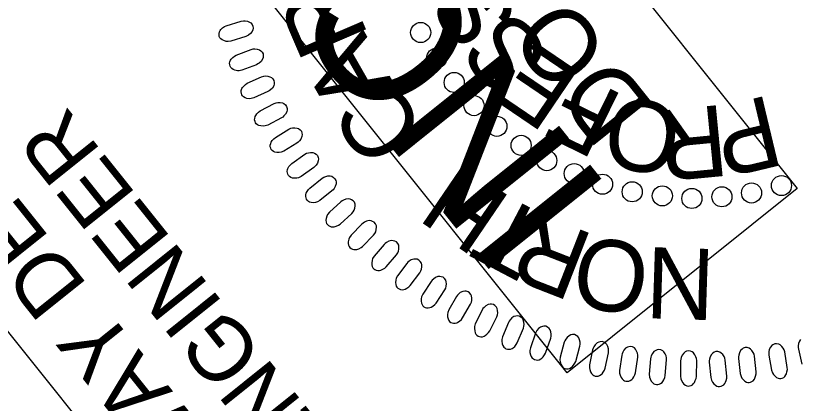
# Model space of a CAD drawing. Extents: x 473437 to 475344, y 504319 to 506318.
# Drawn here: x 473584.9 to 473647.5, y 505540.2 to 505571.1 of the extents above; entities that cross this region are included whole.
import ezdxf

# ---------------------------------------------------------------- set-up
doc = ezdxf.new("R2010")
doc.units = 0
for name, color, linetype in [('Sheet PE Seal Cell', 7, 'Continuous'), ('Sheet Plan CELL', 7, 'Continuous'), ('Sheet Sticker Incomplete CELL', 7, 'Continuous')]:
    doc.layers.add(name, color=color, linetype=linetype)

msp = doc.modelspace()

# ---------------------------------------------------------------- linework, layer by layer
at = {"layer": 'Sheet PE Seal Cell'}
for points in [[(473603.245, 505569.425), (473602.073, 505569.065), (473601.852, 505569.037), (473601.703, 505569.046), (473601.508, 505569.103), (473601.374, 505569.164), (473601.265, 505569.248), (473601.197, 505569.336), (473601.144, 505569.437), (473601.131, 505569.55), (473601.125, 505569.674), (473601.151, 505569.791), (473601.216, 505569.921), (473601.274, 505570.001), (473601.397, 505570.109), (473601.551, 505570.22), (473601.698, 505570.288), (473602.897, 505570.663), (473603.066, 505570.691), (473603.212, 505570.689), (473603.391, 505570.65), (473603.558, 505570.585), (473603.662, 505570.515), (473603.765, 505570.382), (473603.828, 505570.245), (473603.834, 505570.091), (473603.817, 505569.976), (473603.759, 505569.825), (473603.631, 505569.661), (473603.48, 505569.544), (473603.365, 505569.478)], [(473604.098, 505567.183), (473602.95, 505566.75), (473602.732, 505566.708), (473602.583, 505566.708), (473602.384, 505566.753), (473602.248, 505566.805), (473602.133, 505566.882), (473602.059, 505566.966), (473602.001, 505567.064), (473601.98, 505567.176), (473601.966, 505567.298), (473601.985, 505567.418), (473602.041, 505567.55), (473602.095, 505567.634), (473602.211, 505567.75), (473602.358, 505567.869), (473602.5, 505567.947), (473603.673, 505568.397), (473603.839, 505568.436), (473603.986, 505568.443), (473604.167, 505568.416), (473604.337, 505568.359), (473604.446, 505568.297), (473604.558, 505568.171), (473604.629, 505568.038), (473604.644, 505567.884), (473604.634, 505567.769), (473604.586, 505567.615), (473604.47, 505567.443), (473604.325, 505567.316), (473604.214, 505567.243)], [(473605.019, 505565.038), (473603.9, 505564.534), (473603.685, 505564.478), (473603.536, 505564.468), (473603.335, 505564.501), (473603.196, 505564.544), (473603.077, 505564.614), (473602.997, 505564.693), (473602.932, 505564.787), (473602.905, 505564.897), (473602.883, 505565.019), (473602.895, 505565.138), (473602.943, 505565.275), (473602.991, 505565.362), (473603.1, 505565.485), (473603.239, 505565.613), (473603.375, 505565.7), (473604.518, 505566.222), (473604.682, 505566.271), (473604.827, 505566.287), (473605.009, 505566.272), (473605.183, 505566.227), (473605.296, 505566.171), (473605.415, 505566.052), (473605.494, 505565.924), (473605.519, 505565.772), (473605.517, 505565.656), (473605.478, 505565.499), (473605.373, 505565.32), (473605.236, 505565.185), (473605.131, 505565.105)], [(473606.089, 505562.942), (473605.005, 505562.369), (473604.793, 505562.3), (473604.645, 505562.281), (473604.443, 505562.301), (473604.301, 505562.335), (473604.178, 505562.397), (473604.094, 505562.471), (473604.023, 505562.561), (473603.989, 505562.669), (473603.959, 505562.789), (473603.963, 505562.91), (473604.003, 505563.049), (473604.045, 505563.138), (473604.146, 505563.268), (473604.277, 505563.405), (473604.408, 505563.5), (473605.515, 505564.093), (473605.675, 505564.152), (473605.82, 505564.178), (473606.003, 505564.173), (473606.179, 505564.139), (473606.295, 505564.09), (473606.421, 505563.98), (473606.508, 505563.857), (473606.543, 505563.706), (473606.548, 505563.59), (473606.519, 505563.431), (473606.425, 505563.246), (473606.298, 505563.103), (473606.197, 505563.016)], [(473607.327, 505560.936), (473606.281, 505560.297), (473606.074, 505560.214), (473605.928, 505560.186), (473605.725, 505560.193), (473605.58, 505560.219), (473605.454, 505560.273), (473605.365, 505560.341), (473605.29, 505560.426), (473605.248, 505560.533), (473605.211, 505560.65), (473605.208, 505560.77), (473605.238, 505560.912), (473605.275, 505561.004), (473605.367, 505561.14), (473605.49, 505561.284), (473605.614, 505561.387), (473606.682, 505562.049), (473606.838, 505562.118), (473606.98, 505562.153), (473607.164, 505562.16), (473607.341, 505562.137), (473607.46, 505562.096), (473607.593, 505561.993), (473607.688, 505561.876), (473607.732, 505561.727), (473607.744, 505561.612), (473607.726, 505561.451), (473607.643, 505561.261), (473607.525, 505561.11), (473607.43, 505561.017)], [(473608.667, 505558.983), (473607.662, 505558.278), (473607.461, 505558.182), (473607.317, 505558.145), (473607.114, 505558.14), (473606.968, 505558.156), (473606.838, 505558.202), (473606.746, 505558.265), (473606.665, 505558.346), (473606.617, 505558.449), (473606.573, 505558.564), (473606.562, 505558.684), (473606.583, 505558.827), (473606.614, 505558.921), (473606.698, 505559.063), (473606.811, 505559.214), (473606.928, 505559.325), (473607.953, 505560.052), (473608.104, 505560.132), (473608.244, 505560.175), (473608.426, 505560.193), (473608.605, 505560.181), (473608.727, 505560.148), (473608.866, 505560.054), (473608.968, 505559.943), (473609.021, 505559.797), (473609.04, 505559.683), (473609.031, 505559.522), (473608.961, 505559.327), (473608.853, 505559.168), (473608.764, 505559.069)], [(473610.12, 505557.124), (473609.162, 505556.358), (473608.968, 505556.25), (473608.825, 505556.204), (473608.623, 505556.186), (473608.477, 505556.193), (473608.344, 505556.231), (473608.248, 505556.287), (473608.162, 505556.363), (473608.108, 505556.462), (473608.056, 505556.575), (473608.038, 505556.693), (473608.05, 505556.838), (473608.076, 505556.935), (473608.15, 505557.08), (473608.253, 505557.24), (473608.364, 505557.357), (473609.34, 505558.147), (473609.487, 505558.236), (473609.624, 505558.288), (473609.804, 505558.317), (473609.984, 505558.317), (473610.106, 505558.291), (473610.251, 505558.205), (473610.36, 505558.101), (473610.422, 505557.96), (473610.449, 505557.847), (473610.451, 505557.685), (473610.393, 505557.486), (473610.295, 505557.321), (473610.212, 505557.217)], [(473610.824, 505556.259), (473609.916, 505555.434), (473609.779, 505555.259), (473609.711, 505555.127), (473609.66, 505554.929), (473609.644, 505554.784), (473609.661, 505554.647), (473609.701, 505554.543), (473609.763, 505554.446), (473609.853, 505554.377), (473609.955, 505554.309), (473610.07, 505554.271), (473610.214, 505554.261), (473610.313, 505554.271), (473610.469, 505554.321), (473610.643, 505554.397), (473610.775, 505554.488), (473611.711, 505555.328), (473611.821, 505555.458), (473611.894, 505555.585), (473611.952, 505555.759), (473611.98, 505555.936), (473611.974, 505556.061), (473611.912, 505556.218), (473611.827, 505556.342), (473611.696, 505556.426), (473611.589, 505556.47), (473611.43, 505556.496), (473611.224, 505556.471), (473611.046, 505556.4), (473610.93, 505556.335)], [(473612.506, 505554.482), (473611.652, 505553.602), (473611.525, 505553.418), (473611.466, 505553.282), (473611.428, 505553.082), (473611.421, 505552.935), (473611.446, 505552.801), (473611.494, 505552.699), (473611.56, 505552.606), (473611.655, 505552.543), (473611.761, 505552.481), (473611.878, 505552.451), (473612.022, 505552.449), (473612.121, 505552.465), (473612.273, 505552.525), (473612.441, 505552.613), (473612.569, 505552.711), (473613.449, 505553.608), (473613.551, 505553.745), (473613.616, 505553.877), (473613.663, 505554.054), (473613.68, 505554.232), (473613.665, 505554.357), (473613.595, 505554.509), (473613.501, 505554.628), (473613.366, 505554.703), (473613.256, 505554.74), (473613.096, 505554.757), (473612.892, 505554.719), (473612.719, 505554.637), (473612.607, 505554.564)], [(473614.281, 505552.853), (473613.484, 505551.921), (473613.37, 505551.73), (473613.318, 505551.59), (473613.293, 505551.388), (473613.296, 505551.242), (473613.329, 505551.108), (473613.383, 505551.01), (473613.455, 505550.921), (473613.553, 505550.864), (473613.663, 505550.809), (473613.782, 505550.786), (473613.927, 505550.794), (473614.024, 505550.816), (473614.172, 505550.886), (473614.334, 505550.983), (473614.455, 505551.09), (473615.277, 505552.04), (473615.371, 505552.183), (473615.428, 505552.318), (473615.463, 505552.498), (473615.468, 505552.677), (473615.446, 505552.801), (473615.366, 505552.949), (473615.265, 505553.06), (473615.126, 505553.128), (473615.014, 505553.158), (473614.853, 505553.165), (473614.652, 505553.114), (473614.484, 505553.021), (473614.377, 505552.942)], [(473616.09, 505551.348), (473615.353, 505550.368), (473615.251, 505550.17), (473615.208, 505550.027), (473615.196, 505549.824), (473615.208, 505549.678), (473615.25, 505549.547), (473615.309, 505549.451), (473615.387, 505549.369), (473615.488, 505549.317), (473615.602, 505549.269), (473615.722, 505549.254), (473615.865, 505549.271), (473615.961, 505549.298), (473616.105, 505549.378), (473616.26, 505549.485), (473616.374, 505549.599), (473617.136, 505550.599), (473617.22, 505550.748), (473617.268, 505550.887), (473617.292, 505551.068), (473617.286, 505551.247), (473617.256, 505551.369), (473617.167, 505551.512), (473617.059, 505551.617), (473616.916, 505551.676), (473616.803, 505551.699), (473616.641, 505551.695), (473616.444, 505551.631), (473616.282, 505551.528), (473616.18, 505551.443)], [(473618.033, 505549.914), (473617.359, 505548.889), (473617.269, 505548.686), (473617.236, 505548.54), (473617.236, 505548.337), (473617.257, 505548.192), (473617.307, 505548.064), (473617.373, 505547.972), (473617.455, 505547.894), (473617.56, 505547.849), (473617.676, 505547.809), (473617.796, 505547.801), (473617.939, 505547.826), (473618.033, 505547.861), (473618.171, 505547.948), (473618.32, 505548.066), (473618.427, 505548.187), (473619.123, 505549.232), (473619.197, 505549.386), (473619.237, 505549.527), (473619.25, 505549.71), (473619.233, 505549.888), (473619.196, 505550.008), (473619.097, 505550.145), (473618.983, 505550.243), (473618.837, 505550.292), (473618.721, 505550.308), (473618.561, 505550.295), (473618.368, 505550.219), (473618.213, 505550.106), (473618.116, 505550.014)], [(473620.045, 505548.706), (473619.437, 505547.641), (473619.361, 505547.431), (473619.336, 505547.285), (473619.35, 505547.082), (473619.379, 505546.938), (473619.437, 505546.814), (473619.508, 505546.727), (473619.596, 505546.654), (473619.703, 505546.616), (473619.822, 505546.582), (473619.942, 505546.582), (473620.083, 505546.617), (473620.174, 505546.657), (473620.307, 505546.753), (473620.448, 505546.879), (473620.546, 505547.006), (473621.176, 505548.094), (473621.241, 505548.252), (473621.271, 505548.396), (473621.273, 505548.579), (473621.245, 505548.755), (473621.2, 505548.873), (473621.093, 505549.003), (473620.973, 505549.094), (473620.824, 505549.133), (473620.708, 505549.142), (473620.548, 505549.119), (473620.36, 505549.032), (473620.213, 505548.908), (473620.123, 505548.811)], [(473622.097, 505547.635), (473621.556, 505546.534), (473621.493, 505546.321), (473621.479, 505546.172), (473621.504, 505545.971), (473621.544, 505545.83), (473621.609, 505545.709), (473621.685, 505545.627), (473621.777, 505545.559), (473621.887, 505545.528), (473622.007, 505545.502), (473622.127, 505545.509), (473622.265, 505545.553), (473622.354, 505545.598), (473622.48, 505545.703), (473622.613, 505545.838), (473622.704, 505545.971), (473623.264, 505547.096), (473623.319, 505547.258), (473623.34, 505547.403), (473623.329, 505547.586), (473623.29, 505547.761), (473623.238, 505547.875), (473623.124, 505547.998), (473622.998, 505548.082), (473622.847, 505548.111), (473622.731, 505548.113), (473622.573, 505548.08), (473622.391, 505547.98), (473622.251, 505547.849), (473622.167, 505547.745)], [(473624.19, 505546.643), (473623.72, 505545.51), (473623.67, 505545.292), (473623.665, 505545.144), (473623.703, 505544.944), (473623.751, 505544.806), (473623.824, 505544.689), (473623.905, 505544.612), (473624.001, 505544.551), (473624.112, 505544.526), (473624.234, 505544.508), (473624.354, 505544.523), (473624.489, 505544.575), (473624.575, 505544.626), (473624.694, 505544.738), (473624.819, 505544.881), (473624.9, 505545.02), (473625.389, 505546.178), (473625.433, 505546.342), (473625.445, 505546.489), (473625.424, 505546.67), (473625.374, 505546.842), (473625.315, 505546.953), (473625.192, 505547.069), (473625.062, 505547.144), (473624.909, 505547.165), (473624.793, 505547.159), (473624.637, 505547.116), (473624.462, 505547.005), (473624.331, 505546.865), (473624.254, 505546.757)], [(473626.342, 505545.781), (473625.944, 505544.621), (473625.908, 505544.401), (473625.912, 505544.253), (473625.962, 505544.055), (473626.019, 505543.92), (473626.099, 505543.809), (473626.185, 505543.737), (473626.285, 505543.682), (473626.398, 505543.663), (473626.52, 505543.653), (473626.639, 505543.676), (473626.77, 505543.736), (473626.853, 505543.792), (473626.965, 505543.912), (473627.079, 505544.063), (473627.153, 505544.206), (473627.568, 505545.392), (473627.602, 505545.56), (473627.605, 505545.707), (473627.571, 505545.887), (473627.511, 505546.055), (473627.445, 505546.162), (473627.316, 505546.269), (473627.181, 505546.337), (473627.027, 505546.348), (473626.911, 505546.334), (473626.759, 505546.282), (473626.591, 505546.16), (473626.469, 505546.011), (473626.399, 505545.899)], [(473628.65, 505545.066), (473628.325, 505543.883), (473628.303, 505543.661), (473628.316, 505543.513), (473628.38, 505543.319), (473628.445, 505543.188), (473628.532, 505543.082), (473628.622, 505543.015), (473628.725, 505542.967), (473628.838, 505542.956), (473628.961, 505542.953), (473629.078, 505542.983), (473629.206, 505543.052), (473629.284, 505543.113), (473629.389, 505543.24), (473629.494, 505543.396), (473629.558, 505543.544), (473629.898, 505544.754), (473629.921, 505544.924), (473629.915, 505545.07), (473629.871, 505545.248), (473629.799, 505545.412), (473629.727, 505545.515), (473629.591, 505545.614), (473629.452, 505545.673), (473629.297, 505545.674), (473629.184, 505545.653), (473629.034, 505545.591), (473628.874, 505545.459), (473628.762, 505545.304), (473628.699, 505545.186)], [(473630.909, 505544.465), (473630.66, 505543.264), (473630.652, 505543.042), (473630.674, 505542.895), (473630.75, 505542.706), (473630.822, 505542.579), (473630.916, 505542.478), (473631.01, 505542.418), (473631.116, 505542.375), (473631.23, 505542.372), (473631.353, 505542.377), (473631.468, 505542.414), (473631.591, 505542.491), (473631.665, 505542.556), (473631.762, 505542.689), (473631.857, 505542.852), (473631.912, 505543.005), (473632.175, 505544.233), (473632.187, 505544.404), (473632.171, 505544.549), (473632.116, 505544.724), (473632.035, 505544.883), (473631.956, 505544.981), (473631.814, 505545.072), (473631.672, 505545.122), (473631.518, 505545.113), (473631.405, 505545.086), (473631.26, 505545.014), (473631.109, 505544.872), (473631.007, 505544.71), (473630.951, 505544.589)], [(473644.961, 505544.048), (473645.17, 505542.839), (473645.245, 505542.63), (473645.32, 505542.501), (473645.46, 505542.353), (473645.574, 505542.261), (473645.698, 505542.202), (473645.808, 505542.181), (473645.922, 505542.18), (473646.029, 505542.219), (473646.142, 505542.269), (473646.235, 505542.346), (473646.32, 505542.462), (473646.366, 505542.551), (473646.407, 505542.71), (473646.435, 505542.897), (473646.43, 505543.058), (473646.222, 505544.297), (473646.171, 505544.46), (473646.103, 505544.59), (473645.987, 505544.732), (473645.853, 505544.851), (473645.743, 505544.913), (473645.578, 505544.945), (473645.428, 505544.938), (473645.287, 505544.874), (473645.193, 505544.807), (473645.084, 505544.687), (473644.996, 505544.5), (473644.96, 505544.311), (473644.953, 505544.178)], [(473633.228, 505544.031), (473633.054, 505542.817), (473633.06, 505542.595), (473633.092, 505542.448), (473633.179, 505542.265), (473633.259, 505542.143), (473633.359, 505542.048), (473633.457, 505541.993), (473633.565, 505541.958), (473633.679, 505541.962), (473633.802, 505541.975), (473633.914, 505542.019), (473634.032, 505542.103), (473634.103, 505542.173), (473634.19, 505542.312), (473634.275, 505542.481), (473634.319, 505542.635), (473634.505, 505543.879), (473634.507, 505544.05), (473634.482, 505544.194), (473634.416, 505544.365), (473634.325, 505544.52), (473634.24, 505544.612), (473634.093, 505544.693), (473633.947, 505544.734), (473633.794, 505544.715), (473633.683, 505544.681), (473633.543, 505544.601), (473633.401, 505544.45), (473633.309, 505544.281), (473633.261, 505544.158)], [(473635.523, 505543.739), (473635.426, 505542.517), (473635.446, 505542.295), (473635.487, 505542.151), (473635.585, 505541.973), (473635.673, 505541.856), (473635.779, 505541.768), (473635.88, 505541.72), (473635.99, 505541.691), (473636.103, 505541.702), (473636.225, 505541.723), (473636.334, 505541.773), (473636.446, 505541.865), (473636.512, 505541.94), (473636.592, 505542.083), (473636.665, 505542.258), (473636.701, 505542.415), (473636.807, 505543.667), (473636.798, 505543.837), (473636.765, 505543.98), (473636.688, 505544.147), (473636.587, 505544.294), (473636.497, 505544.382), (473636.345, 505544.454), (473636.198, 505544.486), (473636.045, 505544.458), (473635.937, 505544.417), (473635.802, 505544.327), (473635.67, 505544.167), (473635.588, 505543.994), (473635.549, 505543.867)], [(473637.926, 505543.596), (473637.906, 505542.37), (473637.94, 505542.149), (473637.99, 505542.009), (473638.099, 505541.837), (473638.194, 505541.726), (473638.305, 505541.645), (473638.409, 505541.604), (473638.521, 505541.582), (473638.633, 505541.599), (473638.753, 505541.628), (473638.859, 505541.685), (473638.965, 505541.783), (473639.027, 505541.862), (473639.096, 505542.011), (473639.159, 505542.19), (473639.184, 505542.348), (473639.212, 505543.605), (473639.193, 505543.775), (473639.15, 505543.915), (473639.063, 505544.076), (473638.953, 505544.217), (473638.857, 505544.299), (473638.701, 505544.361), (473638.553, 505544.383), (473638.402, 505544.346), (473638.297, 505544.298), (473638.168, 505544.201), (473638.046, 505544.033), (473637.975, 505543.855), (473637.944, 505543.725)], [(473640.208, 505543.469), (473640.332, 505542.249), (473640.392, 505542.035), (473640.457, 505541.901), (473640.586, 505541.743), (473640.694, 505541.644), (473640.813, 505541.577), (473640.921, 505541.547), (473641.035, 505541.539), (473641.145, 505541.57), (473641.261, 505541.612), (473641.359, 505541.681), (473641.453, 505541.791), (473641.504, 505541.877), (473641.556, 505542.033), (473641.598, 505542.218), (473641.604, 505542.378), (473641.484, 505543.629), (473641.445, 505543.796), (473641.386, 505543.93), (473641.28, 505544.08), (473641.155, 505544.207), (473641.05, 505544.276), (473640.888, 505544.32), (473640.737, 505544.325), (473640.592, 505544.27), (473640.493, 505544.21), (473640.377, 505544.098), (473640.275, 505543.918), (473640.226, 505543.732), (473640.21, 505543.6)], [(473642.546, 505543.785), (473642.68, 505542.566), (473642.741, 505542.352), (473642.808, 505542.219), (473642.938, 505542.062), (473643.046, 505541.964), (473643.166, 505541.896), (473643.275, 505541.869), (473643.389, 505541.861), (473643.498, 505541.893), (473643.613, 505541.936), (473643.711, 505542.007), (473643.804, 505542.117), (473643.855, 505542.203), (473643.906, 505542.359), (473643.946, 505542.544), (473643.95, 505542.705), (473643.821, 505543.955), (473643.78, 505544.121), (473643.72, 505544.255), (473643.614, 505544.404), (473643.487, 505544.53), (473643.382, 505544.599), (473643.219, 505544.641), (473643.068, 505544.645), (473642.924, 505544.589), (473642.826, 505544.528), (473642.71, 505544.415), (473642.61, 505544.234), (473642.562, 505544.048), (473642.547, 505543.915)]]:
    msp.add_lwpolyline(points, close=True, dxfattribs=at)
msp.add_lwpolyline([(473647.495, 505545.281), (473647.395, 505545.155), (473647.318, 505544.962), (473647.295, 505544.772), (473647.296, 505544.639), (473647.311, 505544.509), (473647.597, 505543.316)], dxfattribs=at)
for centre in [(473617.199, 505569.751), (473618.474, 505567.711), (473619.872, 505565.771), (473621.452, 505563.924), (473623.28, 505562.276), (473625.207, 505560.759), (473627.253, 505559.54), (473629.44, 505558.505), (473631.698, 505557.66), (473645.966, 505557.55), (473634.067, 505557.057), (473636.468, 505556.734), (473638.825, 505556.529), (473641.22, 505556.66), (473643.578, 505556.965)]:
    msp.add_circle(centre, 0.801, dxfattribs=at)
at = {"layer": 'Sheet Plan CELL'}
msp.add_lwpolyline([(473619.893, 505501.436), (473557.377, 505579.55), (473645.22, 505649.853), (473707.709, 505571.734)], close=True, dxfattribs=at)
at = {"layer": 'Sheet Sticker Incomplete CELL'}
msp.add_lwpolyline([(473647.22, 505557.313), (473628.873, 505542.629), (473537.02, 505657.398), (473555.367, 505672.082)], close=True, dxfattribs=at)

# ---------------------------------------------------------------- texts
at = {"layer": 'Sheet PE Seal Cell'}
for s, rotation, p in [('S', 122.02046, (473625.236, 505570.88)), ('R', 113.28019, (473613.087, 505569.434)), ('S', 129.96025, (473627.728, 505567.929)), ('A', 119.76954, (473615.095, 505565.653)), ('E', 145.83985, (473630.206, 505566.368)), ('C', 126.2589, (473617.792, 505561.951)), ('F', 153.77965, (473633.526, 505564.682)), ('O', 169.65924, (473638.286, 505563.757)), ('P', 193.47864, (473645.024, 505564.794)), ('R', 185.53884, (473641.345, 505564.01)), ('H', 145.72697, (473624.577, 505556.487)), ('T', 152.21633, (473627.664, 505554.886)), ('R', 158.70569, (473631.174, 505553.571)), ('O', 171.6844, (473635.71, 505552.75)), ('N', 178.17375, (473640.733, 505552.483))]:
    msp.add_text(s, height=5.669, rotation=rotation, dxfattribs=at).set_placement(p)
at = {"layer": 'Sheet Plan CELL'}
for s, p in [('ROADWAY DESIGN', (473613.486, 505521.125)), ('ENGINEER', (473610.631, 505536.755))]:
    msp.add_text(s, height=5.0001, rotation=128.67123, dxfattribs=at).set_placement(p)
at = {"layer": 'Sheet Sticker Incomplete CELL'}
for s, height, p in [('INCOMPLETE PLANS', 11.52, (473632.493, 505556.99)), ('DO NOT USE FOR R/W ACQUISITION', 5.76, (473635.889, 505563.87))]:
    msp.add_text(s, height=height, rotation=128.67122, dxfattribs=at).set_placement(p)

doc.saveas('drawing.dxf')
